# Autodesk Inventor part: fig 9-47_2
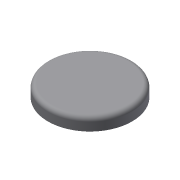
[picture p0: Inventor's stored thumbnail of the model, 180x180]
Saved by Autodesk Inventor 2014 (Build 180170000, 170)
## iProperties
Created: 2013-03
Part Number: fig 9-47_2
Material: Generic
Document SubType Name: Modeling
Designer: CADCIM
Density: 1 g/cm^3
Appearance: Default
Author: CADCIM
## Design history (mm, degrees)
sketch "Sketch1"
  geometry: C1 r 2.5 at (0, 0); 1 further point
  constraints: 1 centre point, 1 coincident
  dimensions: "d0" = 5 diameter of C1
extrude "Extrusion1" new body sketch "Sketch1" distance "d2" = 0.75; taper "d3" = 0 deg
fillet "Fillet1" dims "d4" = 0.25
body "Solid1"
